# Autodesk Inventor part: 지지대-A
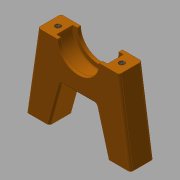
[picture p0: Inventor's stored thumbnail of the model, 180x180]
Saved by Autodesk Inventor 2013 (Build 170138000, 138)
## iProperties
Created: 2018-01
Part Number: 지지대-A
Material: 알루미늄 6061
Document SubType Name: Modeling
Designer: mduedu
Density: 2.71 g/cm^3
Author: mduedu
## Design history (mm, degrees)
sketch "스케치1"
  geometry: L1 (-22.5, 0)-(22.5, 0); L2 (22.5, 0)-(17.5, 34); L3 (17.5, 34)-(-17.5, 34); L4 (-17.5, 34)-(-22.5, 0); 3 further points
  constraints: 8 end point, 2 midpoint, 1 coincident, 1 horizontal, 1 parallel, 1 vertical alignment
  dimensions: "d0" = 45 distance of L1.start L1.end; "d3" = 35 distance of L2.end L3.end; "d4" = 34 vertical distance of L1.end L2.end
extrude "돌출1" new body sketch "스케치1" stored distance "d5" = 10; taper "d6" = 0 deg
sketch "스케치2"
  geometry: L1 (-12.5, 0)-(12.5, 0); L2 (12.5, 0)-(7.5, 18); L3 (7.5, 18)-(-7.5, 18); L4 (-7.5, 18)-(-12.5, 0); L5 (-22.5, 0)-(22.5, 0) reference; 4 further points
  constraints: 8 end point, 4 midpoint, 1 horizontal, 1 parallel, 1 vertical alignment
  dimensions: "d7" = 10 distance of L1.start L5.start; "d8" = 10 distance of L1.end L5.end (derived); "d9" = 15 distance of L2.end L3.end; "d10" = 18 distance between parallel lines of L1 L3
extrude "돌출2" cut sketch "스케치2" stored distance "d11" = 10; taper "d12" = 0 deg
sketch "스케치3"
  geometry: L1 (-17.5, 34)-(17.5, 34) reference; C1 r 11 at (0, 34); C2 r 9 at (0, 34); 1 further point
  constraints: 2 centre point, 1 coincident, 1 midpoint
  dimensions: "d13" = 22 diameter of C1; "d16" = 18 diameter of C2
extrude "돌출3" cut sketch "스케치3" stored distance "d14" = 7; taper "d15" = 0 deg
extrude "돌출4" cut sketch "스케치3" stored distance "d17" = 7; taper "d18" = 0 deg
fillet "모깎기1" dims "d19" = 0.3
fillet "모깎기2" dims "d20" = 1
fillet "모깎기3" dims "d21" = 1
fillet "모깎기4" dims "d22" = 1
sketch "스케치4"
  geometry: 2 further points
  constraints: 2 other
hole "구멍1" sketch "스케치4" at (-22.771, -3.5), (4.771, -3.5) diameter "d23" = 2.459; stored, may be unused: countersink angle "d27" = 90 deg, drill point angle "d29" = 120 deg; dims "d24" = 4.5, "d25" = 4, "d26" = 2, "d28" = 6
sketch "스케치5"
  geometry: 4 further points
  constraints: 4 other
hole "구멍2" sketch "스케치5" at (40, 4), (5, -27), (40, -27), (5, 4) diameter "d30" = 2.459; stored, may be unused: countersink angle "d34" = 90 deg, drill point angle "d36" = 120 deg; dims "d31" = 6.9, "d32" = 4, "d33" = 2, "d35" = 8.4
node "솔리드1"
